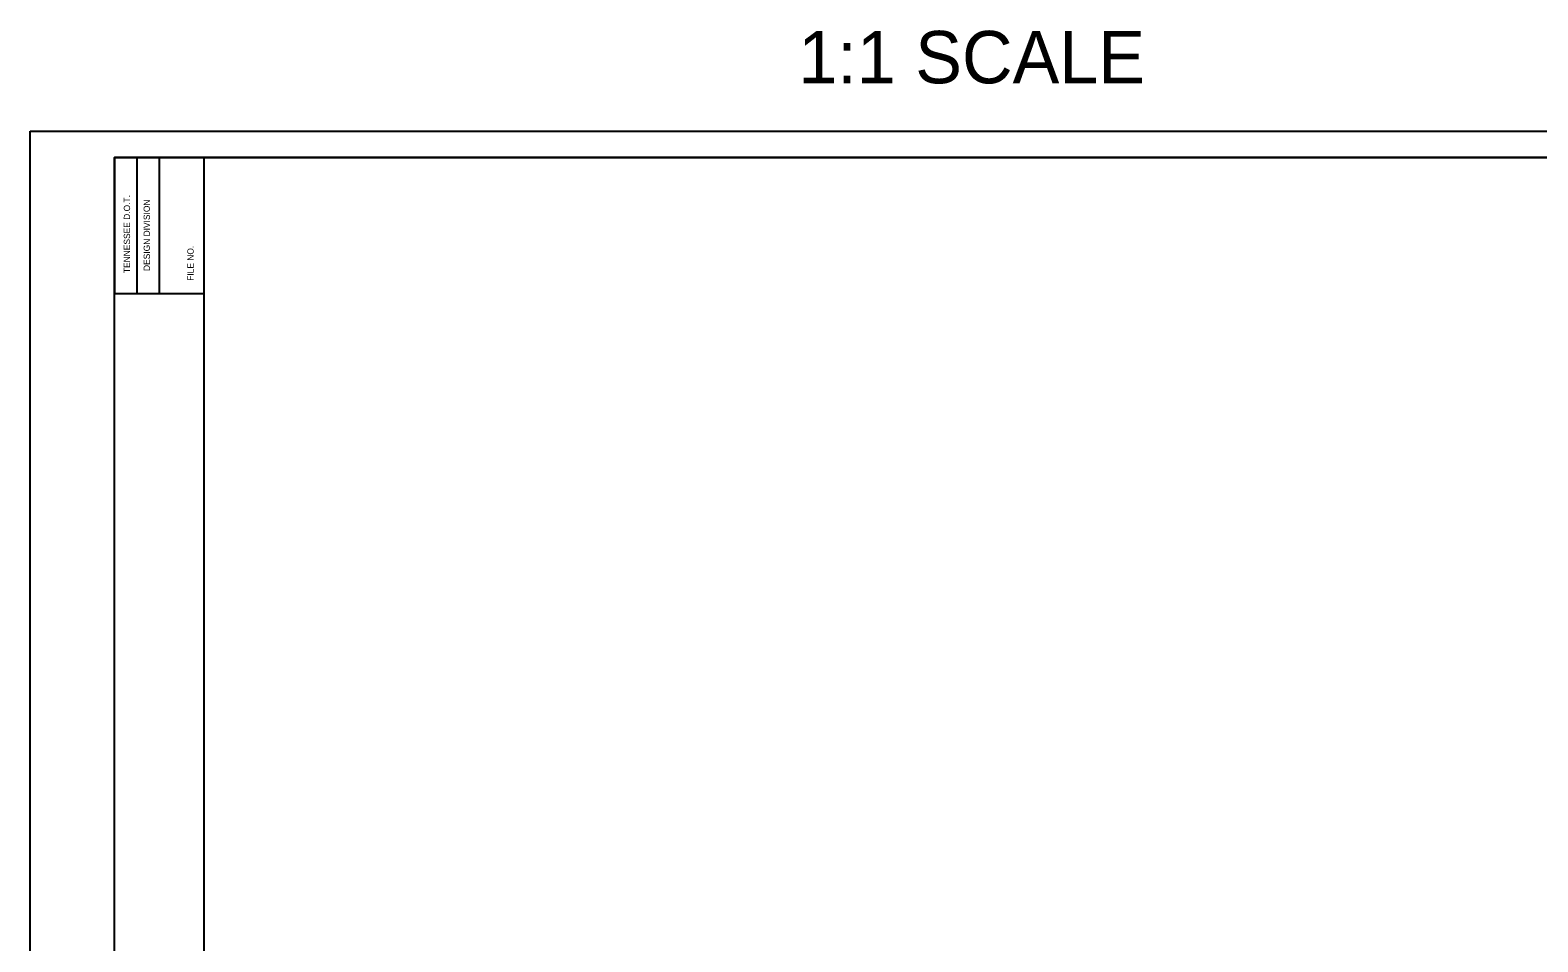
# Model space of a CAD drawing. Extents: x 1623795.1 to 1623879, y 427353.8 to 427391.8.
# Drawn here: x 1623834.9 to 1623863.67, y 427374.38 to 427391.79 of the extents above; entities that cross this region are included whole.
import ezdxf

# ---------------------------------------------------------------- set-up
doc = ezdxf.new("R2010")
doc.units = 0
for name, color, linetype in [('DESIGN - PUBLIC HEARING - Shapes', 7, 'Continuous'), ('DESIGN - SCRATCH - User 1', 7, 'Continuous'), ('DESIGN - SHEET - Corner Text', 7, 'Continuous'), ('DESIGN - SHEET - Linework', 7, 'Continuous'), ('DESIGN - SHEET - Plot Shape', 7, 'Continuous')]:
    doc.layers.add(name, color=color, linetype=linetype)

msp = doc.modelspace()

# ---------------------------------------------------------------- linework, layer by layer
at = {"layer": 'DESIGN - PUBLIC HEARING - Shapes'}
msp.add_lwpolyline([(1623838.215, 427368.358), (1623870.215, 427368.358), (1623870.215, 427389.358), (1623838.215, 427389.358)], close=True, dxfattribs=at)
at = {"layer": 'DESIGN - SCRATCH - User 1'}
msp.add_lwpolyline([(1623836.514, 427389.358), (1623870.215, 427389.358), (1623870.215, 427368.358), (1623836.514, 427368.358)], close=True, dxfattribs=at)
at = {"layer": 'DESIGN - SHEET - Linework'}
for p, q in [((1623836.939, 427389.358), (1623836.939, 427386.761)), ((1623837.365, 427389.358), (1623837.365, 427386.761)), ((1623838.215, 427389.358), (1623838.215, 427368.358)), ((1623870.215, 427389.358), (1623838.215, 427389.358))]:
    msp.add_line(p, q, dxfattribs=at)
msp.add_lwpolyline([(1623838.215, 427389.358), (1623836.514, 427389.358), (1623836.514, 427386.761), (1623838.215, 427386.761)], dxfattribs=at)
at = {"layer": 'DESIGN - SHEET - Plot Shape'}
msp.add_lwpolyline([(1623834.903, 427389.858), (1623870.903, 427389.858), (1623870.903, 427367.858), (1623834.903, 427367.858)], close=True, dxfattribs=at)

# ---------------------------------------------------------------- texts
at = {"layer": 'DESIGN - SHEET - Corner Text'}
msp.add_text('1:1 SCALE', height=1, dxfattribs=at).set_placement((1623849.563, 427390.772))
at = {"layer": 'DESIGN - SHEET - Linework'}
for s, height, p in [('TENNESSEE D.O.T.', 0.12001, (1623836.81, 427387.15)), ('DESIGN DIVISION', 0.12001, (1623837.188, 427387.19)), ('FILE NO.', 0.12, (1623838.023, 427387.003))]:
    msp.add_text(s, height=height, rotation=90, dxfattribs=at).set_placement(p)

doc.saveas('drawing.dxf')
